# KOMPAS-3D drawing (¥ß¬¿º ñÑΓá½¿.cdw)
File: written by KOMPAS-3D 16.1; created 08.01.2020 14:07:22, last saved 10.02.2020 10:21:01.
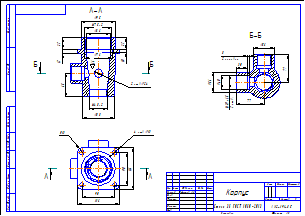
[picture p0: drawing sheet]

Sheet 1: A3, landscape

Title block, sheet 1: name: Корпус; material: Сталь 35 ГОСТ 1050-2013; sheets: 1; organisation: АХ2-191-ДБ; sheet format: A3; stored path: D:\ЗАДАЧИ\task_248930  Р\Корпус _ МЧ00.24.01.01.cdw; drawn by: Ефремов А.Л.

Views: Вид 1, Разрез А-А, Разрез Б-Б
Referenced files in D:\ЗАДАЧИ\task_248930  Р\: Корпус _ МЧ00.24.01.01.m3d
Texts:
  Пользователь Windows
Dimensions and other numbers on the sheet: 90; 116; 4 отв.; 13; 88; 48; 65; 2 отв.; 24; 75; 95; 32; 12; 10; 76; 66; 39; 56; 77; 30; 8; 2 канавки; 40; 1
